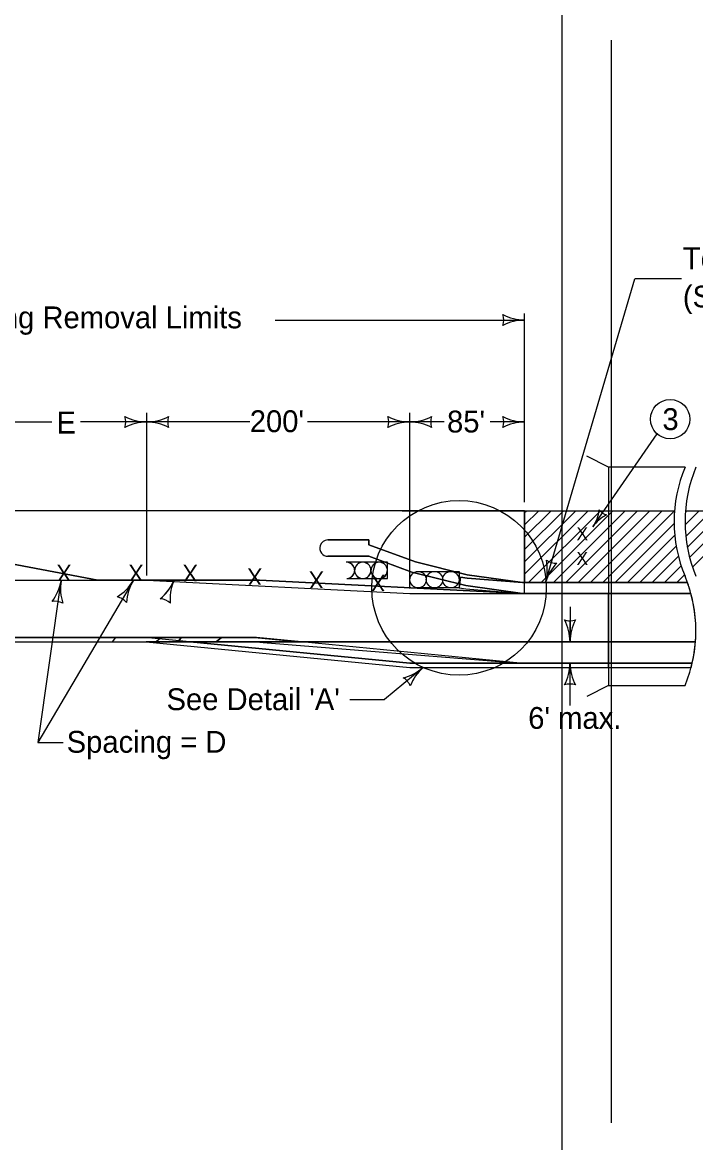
# Model space of a CAD drawing. Extents: x -2135039 to 114557, y -2139150 to -409929.
# Drawn here: x -2132982 to -2132365, y -2138196 to -2137170 of the extents above; entities that cross this region are included whole.
import ezdxf

# ---------------------------------------------------------------- set-up
doc = ezdxf.new("R2010")
doc.units = 0
for name, color, linetype in [('dsnNonPlotable', 7, 'Continuous'), ('dsnStdLabel', 7, 'Continuous'), ('dsnStdLineWork', 7, 'Continuous'), ('dsnStdNote', 7, 'Continuous'), ('dsnStdShading', 7, 'Continuous'), ('Level 2', 7, 'Continuous'), ('StdDimension', 7, 'Continuous')]:
    doc.layers.add(name, color=color, linetype=linetype)

# ---------------------------------------------------------------- blocks, each defined once
blk = doc.blocks.new('LT')
at = {"layer": 'dsnStdLabel'}
for centre, radius, start, end in [((-3.56, 0), 1.64, 342.2666, 17.7333), ((0, 4.25), 4.25, 241.9275, 270), ((0, -4.25), 4.25, 90, 118.0725)]:
    blk.add_arc(centre, radius, start, end, dxfattribs=at)

msp = doc.modelspace()

# ---------------------------------------------------------------- linework, layer by layer
at = {"layer": 'dsnNonPlotable'}
for p, q in [((-2132487.5, -2137085.9), (-2132487.5, -2138555.9)), ((-2132442.5, -2137185.9), (-2132442.5, -2138177.5))]:
    msp.add_line(p, q, dxfattribs=at)
at = {"layer": 'dsnStdLabel'}
for p, q in [((-2132521.7, -2137618.5), (-2132520.1, -2137616.9)), ((-2132521.7, -2137629.8), (-2132508.8, -2137616.9)), ((-2132521.7, -2137641.1), (-2132497.5, -2137616.9)), ((-2132521.7, -2137652.4), (-2132486.2, -2137616.9)), ((-2132521.7, -2137663.7), (-2132474.9, -2137616.9)), ((-2132521.7, -2137675), (-2132463.5, -2137616.9)), ((-2132521.7, -2137616.9), (-2132521.7, -2137682.6)), ((-2132518, -2137682.6), (-2132452.2, -2137616.9)), ((-2132506.6, -2137682.6), (-2132440.9, -2137616.9)), ((-2132495.3, -2137682.6), (-2132429.6, -2137616.9)), ((-2132484, -2137682.6), (-2132418.3, -2137616.9)), ((-2132472.7, -2137682.6), (-2132407, -2137616.9)), ((-2132461.4, -2137682.6), (-2132395.7, -2137616.9)), ((-2132410.9, -2137620.9), (-2132406.9, -2137616.9)), ((-2132410.1, -2137642.7), (-2132384.3, -2137616.9)), ((-2132374.7, -2137629.9), (-2132361.7, -2137616.9)), ((-2132374.4, -2137618.3), (-2132373, -2137616.9)), ((-2132374, -2137640.5), (-2132350.4, -2137616.9)), ((-2132372.6, -2137650.4), (-2132339.1, -2137616.9)), ((-2132370.5, -2137659.7), (-2132327.8, -2137616.9)), ((-2132367.9, -2137668.4), (-2132316.5, -2137616.9)), ((-2132438.8, -2137682.6), (-2132384.7, -2137628.6)), ((-2132450.1, -2137682.6), (-2132410.1, -2137642.7)), ((-2132427.5, -2137682.6), (-2132384.1, -2137639.3)), ((-2132416.1, -2137682.6), (-2132382.8, -2137649.3)), ((-2132404.8, -2137682.6), (-2132380.8, -2137658.6)), ((-2132393.5, -2137682.6), (-2132378.3, -2137667.4)), ((-2132382.2, -2137682.6), (-2132375.2, -2137675.7)), ((-2132626.9, -2137756.4), (-2132869.8, -2137732.9))]:
    msp.add_line(p, q, dxfattribs=at)
for centre, radius in [((-2132581.8, -2137687.5), 80), ((-2132619.3, -2137680), 7.5), ((-2132604.3, -2137680), 7.5), ((-2132589.3, -2137680), 7.5)]:
    msp.add_circle(centre, radius, dxfattribs=at)
at = {"layer": 'dsnStdLineWork'}
for p, q in [((-2132444.7, -2137576.9), (-2132464.7, -2137566.9)), ((-2133016.2, -2137680.6), (-2132868, -2137680.6)), ((-2132868, -2137680.6), (-2132626.9, -2137692.6)), ((-2132523.6, -2137682.6), (-2132372.5, -2137682.6)), ((-2132626.9, -2137692.6), (-2132523.6, -2137692.6)), ((-2132369.3, -2137692.6), (-2132523.6, -2137692.6)), ((-2134898.2, -2137732.9), (-2132869.8, -2137732.9)), ((-2132868.6, -2137736.9), (-2132542.8, -2137736.9)), ((-2132542.8, -2137736.9), (-2132365.1, -2137736.9)), ((-2132626.9, -2137756.4), (-2132368.1, -2137756.4)), ((-2132444.7, -2137776.9), (-2132464.7, -2137786.9))]:
    msp.add_line(p, q, dxfattribs=at)
for points in [[(-2132374.7, -2137576.9), (-2132444.7, -2137576.9), (-2132444.7, -2137776.9), (-2132374.7, -2137776.9)], [(-2132580.5, -2137677.7), (-2132581.8, -2137687.5), (-2132581.8, -2137687.5)], [(-2132580.5, -2137677.7), (-2132574.3, -2137678.5), (-2132523.6, -2137682.6)], [(-2132581.8, -2137687.5), (-2132575.5, -2137688.3), (-2132523.6, -2137692.6)]]:
    msp.add_lwpolyline(points, dxfattribs=at)
for centre, start, end in [((-2132254.7, -2137626.9), 157.3801, 202.6199), ((-2132244.7, -2137626.9), 157.3801, 202.6199), ((-2132494.7, -2137726.9), 337.3801, 22.6199)]:
    msp.add_arc(centre, 130, start, end, dxfattribs=at)
at = {"layer": 'dsnStdNote'}
msp.add_circle((-2132388.3, -2137533), 18, dxfattribs=at)
at = {"layer": 'dsnStdShading'}
for p, q in [((-2132633.8, -2137616.9), (-2133464.5, -2137616.9)), ((-2132633.8, -2137616.9), (-2132384.3, -2137616.9)), ((-2132374.3, -2137616.9), (-2131855.9, -2137616.9)), ((-2132521.7, -2137641.1), (-2132521.7, -2137629.8)), ((-2132664.5, -2137648), (-2132664.5, -2137643.6)), ((-2132687.1, -2137658.6), (-2132701.9, -2137658.6)), ((-2132701.9, -2137658.6), (-2132687.1, -2137658.6)), ((-2132672.1, -2137658.6), (-2132686.9, -2137658.6)), ((-2132686.9, -2137658.6), (-2132672.1, -2137658.6)), ((-2132664.5, -2137658.6), (-2132671.9, -2137658.6)), ((-2132671.9, -2137658.6), (-2132664.5, -2137658.6)), ((-2133014.4, -2137661.1), (-2132912.9, -2137680.6)), ((-2132912.9, -2137680.6), (-2133014.4, -2137661.1)), ((-2132670.4, -2137664), (-2132685, -2137664)), ((-2132655.4, -2137664), (-2132670.4, -2137664)), ((-2132647.5, -2137664), (-2132655.4, -2137664)), ((-2132647.5, -2137671.1), (-2132647.5, -2137664)), ((-2132521.7, -2137675), (-2132521.7, -2137663.7)), ((-2132684.6, -2137679), (-2132670, -2137679)), ((-2132669.6, -2137679), (-2132654.6, -2137679)), ((-2132654.6, -2137679), (-2132647.5, -2137679)), ((-2132647.5, -2137679), (-2132647.5, -2137671.5)), ((-2132580.5, -2137677.7), (-2132581.8, -2137687.5)), ((-2132521.7, -2137682.6), (-2132521.7, -2137675)), ((-2132912.9, -2137680.6), (-2132797.5, -2137680.6)), ((-2132764.7, -2137680.6), (-2132912.9, -2137680.6)), ((-2132843.3, -2137681), (-2132843.9, -2137682.6)), ((-2132797.5, -2137680.6), (-2132764.7, -2137680.6)), ((-2132764.7, -2137680.6), (-2132523.6, -2137692.6)), ((-2132523.6, -2137692.6), (-2132764.7, -2137680.6)), ((-2132372.5, -2137682.6), (-2132523.6, -2137682.6)), ((-2132521.7, -2137692.7), (-2132521.7, -2137682.6)), ((-2132523.6, -2137692.6), (-2132369.3, -2137692.6)), ((-2132444.7, -2137692.6), (-2132523.6, -2137692.6)), ((-2132523.6, -2137692.6), (-2132521.7, -2137692.7)), ((-2132369.3, -2137692.6), (-2132444.7, -2137692.6)), ((-2132444.7, -2137692.6), (-2132444.7, -2137736.9)), ((-2132444.7, -2137736.9), (-2132444.7, -2137692.6)), ((-2132480.1, -2137736.9), (-2132480.1, -2137717.7)), ((-2133075.9, -2137736.9), (-2132839.3, -2137736.9)), ((-2132836.4, -2137732.9), (-2133072.6, -2137732.9)), ((-2132896.7, -2137732.9), (-2132899.6, -2137736.9)), ((-2132899.6, -2137736.9), (-2132859.9, -2137736.9)), ((-2132854.8, -2137732.9), (-2132896.7, -2137732.9)), ((-2132828.3, -2137736.9), (-2132868.6, -2137736.9)), ((-2132868.6, -2137736.9), (-2132626.9, -2137760.4)), ((-2132868.6, -2137736.9), (-2132626.9, -2137760.4)), ((-2132859.9, -2137736.9), (-2132854.8, -2137732.9)), ((-2132839.3, -2137736.9), (-2132836.4, -2137732.9)), ((-2132836.4, -2137732.9), (-2132839.3, -2137736.9)), ((-2132839.3, -2137736.9), (-2132804.4, -2137736.9)), ((-2132799.5, -2137732.9), (-2132836.4, -2137732.9)), ((-2132626.9, -2137756.4), (-2132828.3, -2137736.9)), ((-2132542.8, -2137736.9), (-2132828.3, -2137736.9)), ((-2132828.3, -2137736.9), (-2132626.9, -2137756.4)), ((-2132799.5, -2137732.9), (-2132804.4, -2137736.9)), ((-2132804.4, -2137736.9), (-2132799.5, -2137732.9)), ((-2132768.8, -2137732.9), (-2132727.6, -2137736.9)), ((-2132726.3, -2137736.9), (-2132767.6, -2137736.9)), ((-2132767.6, -2137736.9), (-2132761.3, -2137737.5)), ((-2132726.3, -2137736.9), (-2132767.4, -2137732.9)), ((-2132761.3, -2137737.5), (-2132525.7, -2137756.4)), ((-2132727.6, -2137736.9), (-2132726.3, -2137736.9)), ((-2132525.7, -2137756.4), (-2132726.3, -2137736.9)), ((-2132726.3, -2137736.9), (-2132542.8, -2137736.9)), ((-2132365.1, -2137736.9), (-2132444.7, -2137736.9)), ((-2132444.7, -2137736.9), (-2132444.7, -2137756.4)), ((-2132444.7, -2137736.9), (-2132365.1, -2137736.9)), ((-2132444.7, -2137756.4), (-2132444.7, -2137736.9)), ((-2132480.1, -2137756.4), (-2132626.9, -2137756.4)), ((-2132626.9, -2137756.4), (-2132489.9, -2137756.4)), ((-2132626.9, -2137760.4), (-2132369.1, -2137760.4)), ((-2132626.9, -2137760.4), (-2132480.3, -2137760.4)), ((-2132525.7, -2137756.4), (-2132368.1, -2137756.4)), ((-2132489.9, -2137756.4), (-2132480.1, -2137756.4)), ((-2132472.1, -2137756.4), (-2132480.1, -2137756.4)), ((-2132480.1, -2137756.4), (-2132472.1, -2137756.4)), ((-2132479.9, -2137760.4), (-2132444.7, -2137760.4)), ((-2132444.7, -2137756.4), (-2132472.1, -2137756.4)), ((-2132472.1, -2137756.4), (-2132444.7, -2137756.4)), ((-2132444.7, -2137756.4), (-2132368.1, -2137756.4)), ((-2132444.7, -2137760.4), (-2132444.7, -2137756.4)), ((-2132444.7, -2137756.4), (-2132444.7, -2137760.4)), ((-2132395.5, -2137760.4), (-2132369.1, -2137760.4)), ((-2132394.5, -2137756.4), (-2132368.1, -2137756.4))]:
    msp.add_line(p, q, dxfattribs=at)
for points in [[(-2132521.7, -2137616.9), (-2132562, -2137616.9), (-2132633.8, -2137616.9)], [(-2132521.7, -2137629.8), (-2132521.7, -2137618.5), (-2132521.7, -2137616.9)], [(-2132702, -2137643.6), (-2132702, -2137643.6), (-2132672, -2137643.6), (-2132672, -2137643.6), (-2132664.5, -2137643.6)], [(-2132664.5, -2137643.6), (-2132672, -2137643.6), (-2132702, -2137643.6)], [(-2132664.5, -2137643.6), (-2132664.5, -2137648), (-2132664.5, -2137648)], [(-2132664.5, -2137648), (-2132621.7, -2137663.6), (-2132574.4, -2137675.5), (-2132523.6, -2137682.6), (-2132521.7, -2137682.6)], [(-2132521.7, -2137682.6), (-2132523.6, -2137682.6), (-2132574.4, -2137675.5), (-2132621.7, -2137663.6), (-2132664.5, -2137648)], [(-2132521.7, -2137663.7), (-2132521.7, -2137652.4), (-2132521.7, -2137641.1)], [(-2132523.6, -2137692.6), (-2132575.6, -2137685.4), (-2132625.1, -2137673), (-2132664.5, -2137658.6)], [(-2132664.5, -2137658.6), (-2132625.1, -2137673), (-2132575.6, -2137685.4), (-2132523.6, -2137692.6)], [(-2132670.4, -2137664), (-2132670.4, -2137664)], [(-2132670.4, -2137664), (-2132670.4, -2137664)], [(-2132655.4, -2137664), (-2132655.4, -2137664)], [(-2132655.4, -2137664), (-2132655.4, -2137664)], [(-2132684.6, -2137679), (-2132684.6, -2137679)], [(-2132677.5, -2137671.1), (-2132677.5, -2137671.1)], [(-2132669.6, -2137679), (-2132669.6, -2137679)], [(-2132662.5, -2137671.1), (-2132662.5, -2137671.1)], [(-2132654.6, -2137679), (-2132654.6, -2137679)], [(-2132654.6, -2137679), (-2132654.6, -2137679)], [(-2132647.5, -2137671.1), (-2132647.5, -2137671.1)], [(-2132523.6, -2137682.6), (-2132574.3, -2137678.5), (-2132580.5, -2137677.7)], [(-2132843.9, -2137682.6), (-2132843.9, -2137682.6)], [(-2132797.5, -2137680.6), (-2132797.5, -2137680.6), (-2132797.2, -2137680.3)], [(-2132581.8, -2137687.5), (-2132575.5, -2137688.3), (-2132524, -2137692.6), (-2132523.6, -2137692.6)], [(-2132523.6, -2137692.6), (-2132523.6, -2137692.6)], [(-2133072.6, -2137732.9), (-2132863.8, -2137732.9), (-2132768.8, -2137732.9)], [(-2132804.4, -2137736.9), (-2132767.6, -2137736.9), (-2132726.3, -2137736.9)], [(-2132767.4, -2137732.9), (-2132768.3, -2137732.9), (-2132799.5, -2137732.9)], [(-2132444.7, -2137736.9), (-2132472.1, -2137736.9), (-2132480.1, -2137736.9), (-2132490.9, -2137736.9), (-2132542.8, -2137736.9)], [(-2132542.8, -2137736.9), (-2132490.9, -2137736.9), (-2132480.1, -2137736.9)], [(-2132480.1, -2137736.9), (-2132472.1, -2137736.9), (-2132444.7, -2137736.9)], [(-2132368.1, -2137756.4), (-2132394.5, -2137756.4), (-2132444.7, -2137756.4)], [(-2132444.7, -2137760.4), (-2132395.5, -2137760.4), (-2132369.1, -2137760.4)]]:
    msp.add_lwpolyline(points, dxfattribs=at)
for centre, radius, start, end in [((-2132702, -2137651.1), 7.5, 163.0498, 270.9263), ((-2132702, -2137651.1), 7.5, 163.0498, 270.9263), ((-2132702, -2137651.1), 7.5, 90, 163.0526), ((-2132702, -2137651.1), 7.5, 90, 163.0526), ((-2132687, -2137651.1), 7.5, 268.9774, 271.0226), ((-2132687, -2137651.1), 7.5, 268.9774, 271.0226), ((-2132672, -2137651.1), 7.5, 269.0651, 270.9349), ((-2132672, -2137651.1), 7.5, 269.0651, 270.9349), ((-2132685, -2137671.5), 7.5, 3.0001, 92.9999), ((-2132685, -2137671.5), 7.5, 2.9957, 90), ((-2132670, -2137671.5), 7.5, 93.0448, 93), ((-2132670, -2137671.5), 7.5, 93.0417, 177.0124), ((-2132670, -2137671.5), 7.5, 2.9957, 92.9969), ((-2132655, -2137671.5), 7.5, 93.006, 182.994), ((-2132655, -2137671.5), 7.5, 92.9969, 177.0124), ((-2132655, -2137671.5), 7.51, 3.1005, 92.8995), ((-2132655, -2137671.5), 7.5, 2.9959, 92.9969), ((-2132685, -2137671.4), 7.55, 273.1403, 356.6811), ((-2132685, -2137671.5), 7.5, 273.0025, 317.9707), ((-2132685, -2137671.4), 7.55, 317.8276, 356.6663), ((-2132670, -2137671.5), 7.5, 183.0131, 269.6775), ((-2132670, -2137671.4), 7.55, 273.1444, 356.677), ((-2132670, -2137671.5), 7.5, 272.9998, 319.0541), ((-2132670, -2137671.4), 7.55, 318.902, 356.5996), ((-2132655, -2137671.5), 7.5, 182.9958, 273.0042), ((-2132655, -2137671.5), 7.5, 183.0813, 273.0025), ((-2132655, -2137671.5), 7.5, 272.9998, 3.0002), ((-2132655, -2137671.5), 7.5, 273.0025, 0), ((-2132882.5, -2137664.6), 42.5, 309.1847, 337.2396), ((-2132882.5, -2137664.6), 42.5, 309.1847, 335.0317), ((-2132804.1, -2137697.5), 42.5, 159.4861, 185.3297), ((-2132804.1, -2137697.5), 42.5, 159.4861, 185.3297), ((-2132804.1, -2137697.5), 42.5, 157.2572, 157.2748), ((-2132762.9, -2137705.3), 42.5, 143.9182, 144.4611), ((-2132762.9, -2137705.3), 42.5, 143.9006, 143.9011), ((-2132831.6, -2137655.3), 42.5, 323.883, 323.9006), ((-2132494.7, -2137726.9), 130, 15.2823, 19.9072), ((-2132857, -2137713.9), 16.4, 49.5238, 84.9905), ((-2132857, -2137713.9), 16.4, 49.5238, 84.9905), ((-2132494.7, -2137726.9), 130, 355.5883, 15.2823), ((-2132480.1, -2137701.3), 16.4, 252.2666, 270), ((-2132522.6, -2137736.9), 42.5, 0.0176, 28.0725), ((-2132437.6, -2137736.9), 42.5, 179.9824, 180), ((-2132494.7, -2137726.9), 130, 346.8816, 355.5883), ((-2132522.6, -2137756.4), 42.5, 354.5995, 360), ((-2132522.6, -2137756.4), 42.5, 359.9824, 360), ((-2132437.6, -2137756.4), 42.5, 180.0176, 185.4005), ((-2132494.7, -2137726.9), 130, 345.0644, 346.8816)]:
    msp.add_arc(centre, radius, start, end, dxfattribs=at)
at = {"layer": 'Level 2'}
for p, q in [((-2132619.3, -2137672.5), (-2132581.8, -2137672.5)), ((-2132581.8, -2137672.5), (-2132581.8, -2137687.5)), ((-2132581.8, -2137687.5), (-2132619.3, -2137687.5))]:
    msp.add_line(p, q, dxfattribs=at)
for centre in [(-2132619.3, -2137680), (-2132619.3, -2137680), (-2132604.3, -2137680), (-2132604.3, -2137680), (-2132589.3, -2137680), (-2132589.3, -2137680)]:
    msp.add_circle(centre, 7.5, dxfattribs=at)
at = {"layer": 'StdDimension'}
for p, q in [((-2132502.6, -2137682.6), (-2132420.8, -2137404.6)), ((-2132378, -2137404.6), (-2132420.8, -2137404.6)), ((-2132750.4, -2137442.2), (-2132521.7, -2137442.2)), ((-2132521.7, -2137608.9), (-2132521.7, -2137436.1)), ((-2133071.8, -2137535.6), (-2132954.9, -2137535.6)), ((-2132773.5, -2137535.6), (-2132928.7, -2137535.6)), ((-2132868, -2137676.2), (-2132868, -2137527.1)), ((-2132626.9, -2137535.6), (-2132720.8, -2137535.6)), ((-2132626.9, -2137688.1), (-2132626.9, -2137527.1)), ((-2132595.4, -2137535.6), (-2132626.9, -2137535.6)), ((-2132521.7, -2137535.6), (-2132553.2, -2137535.6)), ((-2132459.1, -2137631.6), (-2132400.2, -2137546.5)), ((-2132946.6, -2137681), (-2132967.8, -2137829.1)), ((-2132880.6, -2137681), (-2132967.8, -2137829.1)), ((-2132480.1, -2137704.9), (-2132480.1, -2137736.9)), ((-2132490.9, -2137736.9), (-2132472.1, -2137736.9)), ((-2132614.7, -2137760.4), (-2132650, -2137789.6)), ((-2132489.9, -2137756.4), (-2132472.1, -2137756.4)), ((-2132480.1, -2137795.2), (-2132480.1, -2137756.4)), ((-2132682, -2137789.6), (-2132650, -2137789.6)), ((-2132967.8, -2137829.1), (-2132944.7, -2137829.1))]:
    msp.add_line(p, q, dxfattribs=at)
for centre, radius, start, end in [((-2132557.3, -2137442.2), 16.4, 342.2666, 17.7333), ((-2132521.7, -2137399.7), 42.5, 241.9275, 270), ((-2132521.7, -2137484.7), 42.5, 90, 118.0725), ((-2132903.6, -2137535.6), 16.4, 342.2666, 17.7333), ((-2132868, -2137493.1), 42.5, 241.9275, 270), ((-2132868, -2137578.1), 42.5, 90, 118.0725), ((-2132868, -2137493.1), 42.5, 270, 298.0725), ((-2132868, -2137578.1), 42.5, 61.9275, 90), ((-2132832.4, -2137535.6), 16.4, 162.2666, 197.7334), ((-2132662.6, -2137535.6), 16.4, 342.2666, 17.7333), ((-2132626.9, -2137493.1), 42.5, 241.9275, 270), ((-2132626.9, -2137578.1), 42.5, 90, 118.0725), ((-2132626.9, -2137493.1), 42.5, 270, 298.0725), ((-2132626.9, -2137578.1), 42.5, 61.9275, 90), ((-2132591.3, -2137535.6), 16.4, 162.2666, 197.7334), ((-2132557.3, -2137535.6), 16.4, 342.2666, 17.7333), ((-2132521.7, -2137493.1), 42.5, 241.9275, 270), ((-2132521.7, -2137578.1), 42.5, 90, 118.0725), ((-2132543.4, -2137670.6), 42.5, 343.6131, 11.6856), ((-2132461.8, -2137694.6), 42.5, 135.5406, 163.6131), ((-2132492.5, -2137648.5), 16.4, 235.8797, 271.3464), ((-2132988.5, -2137674.1), 42.5, 322.5687, 350.6412), ((-2132904.6, -2137688), 42.5, 170.6412, 198.7137), ((-2132917.2, -2137659.5), 42.5, 301.4319, 329.5044), ((-2132844, -2137702.6), 42.5, 149.5044, 177.5769), ((-2132952.4, -2137716.2), 16.4, 62.9079, 98.3746), ((-2132898.7, -2137711.8), 16.4, 41.7711, 77.2378), ((-2132480.1, -2137701.3), 16.4, 252.2666, 287.7333), ((-2132522.6, -2137736.9), 42.5, 360, 28.0725), ((-2132437.6, -2137736.9), 42.5, 151.9275, 180), ((-2132642.6, -2137728.4), 42.5, 282.974, 311.0465), ((-2132586.8, -2137792.5), 42.5, 131.0465, 159.119), ((-2132522.6, -2137756.4), 42.5, 331.9275, 360), ((-2132437.6, -2137756.4), 42.5, 180, 208.0725), ((-2132641.5, -2137783.8), 16.4, 23.3132, 58.7799), ((-2132480.1, -2137792), 16.4, 72.2666, 107.7334)]:
    msp.add_arc(centre, radius, start, end, dxfattribs=at)

# ---------------------------------------------------------------- block references
at = {"layer": 'StdDimension', "xscale": 7.999600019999, "yscale": 7.999200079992, "rotation": -124.70293665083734}
msp.add_blockref('LT', (-2132459.1, -2137631.6), dxfattribs=at)

# ---------------------------------------------------------------- texts
at = {"layer": 'dsnStdLabel'}
for p in [(-2132474.2, -2137644), (-2132474.2, -2137666.6)]:
    msp.add_text('X', height=12, dxfattribs=at).set_placement(p)
for p in [(-2132937.1, -2137666.2), (-2132871.1, -2137666.2), (-2132821.4, -2137666.4), (-2132762.3, -2137669.7), (-2132705.8, -2137672.5), (-2132649.3, -2137675.3)]:
    msp.add_text('X', height=15, rotation=180, dxfattribs=at).set_placement(p)
at = {"layer": 'dsnStdNote'}
msp.add_text('3', height=20, dxfattribs=at).set_placement((-2132395.4, -2137543))
at = {"layer": 'StdDimension'}
for s, p in [('Temporary Barrier Rail', (-2132376.7, -2137395.7)), ('(See Typical 8210)', (-2132376.7, -2137430.7)), ('Pavement Marking Removal Limits', (-2133194, -2137449.8)), ("200'", (-2132773.6, -2137544.9)), ("85'", (-2132592.8, -2137545.2)), ('E', (-2132950.7, -2137546.2)), ("See Detail 'A'", (-2132849.9, -2137799.5)), ("6' max.", (-2132518.4, -2137816.6)), ('Spacing = D', (-2132941.4, -2137838.5))]:
    msp.add_text(s, height=20, dxfattribs=at).set_placement(p)

doc.saveas('drawing.dxf')
